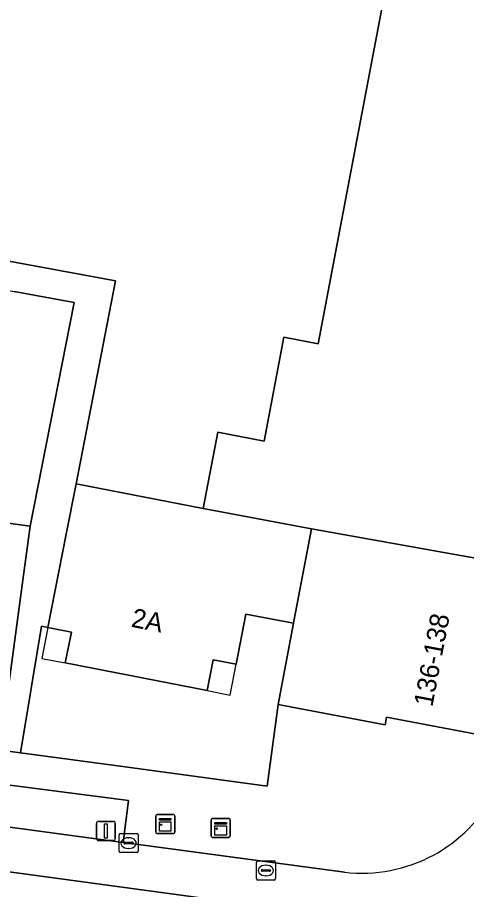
# Model space of a CAD drawing. Extents: x 161402 to 161933, y 381647 to 382315.
# Drawn here: x 161811.25 to 161834.8, y 381674.43 to 381720.22 of the extents above; entities that cross this region are included whole.
import ezdxf

# ---------------------------------------------------------------- set-up
doc = ezdxf.new("R2010")
doc.units = 0
for name, color, linetype in [('IMGEO_Erf', 7, 'Continuous'), ('IMGEO_Fietspad_gesloten', 7, 'Continuous'), ('IMGEO_Groenvoorziening', 7, 'Continuous'), ('IMGEO_Kast', 7, 'Continuous'), ('IMGEO_Kolk', 7, 'Continuous'), ('IMGEO_Lichtmast', 7, 'Continuous'), ('IMGEO_Pand', 7, 'Continuous'), ('IMGEO_Pand_nummerreeks', 7, 'Continuous'), ('IMGEO_Pand_overbouw', 7, 'Continuous'), ('IMGEO_Verkeerseiland_groen', 7, 'Continuous'), ('IMGEO_Voetpad_open', 7, 'Continuous')]:
    doc.layers.add(name, color=color, linetype=linetype)

msp = doc.modelspace()

# ---------------------------------------------------------------- linework, layer by layer
at = {"layer": 'IMGEO_Erf'}
for points in [[(161801.214, 381709.179), (161816.398, 381706.393), (161814.319, 381695.735), (161820.996, 381694.433), (161821.755, 381698.436), (161824.188, 381697.974), (161825.224, 381703.428), (161827.019, 381703.087), (161830.821, 381723.103)], [(161805.528, 381694.375), (161811.92, 381693.508), (161814.221, 381705.25), (161811.08, 381705.825)]]:
    msp.add_lwpolyline(points, dxfattribs=at)
msp.add_lwpolyline([(161824.917, 381684.151), (161825.725, 381688.406), (161823.234, 381688.891), (161822.721, 381686.261), (161821.514, 381686.497), (161821.198, 381684.877), (161813.758, 381686.328), (161814.074, 381687.948), (161812.847, 381688.187), (161812.504, 381688.254), (161811.416, 381681.599), (161816.889, 381680.871), (161824.343, 381679.854)], close=True, dxfattribs=at)
at = {"layer": 'IMGEO_Fietspad_gesloten'}
for points in [[(161816.794, 381676.903), (161801.769, 381678.925), (161797.978, 381679.434), (161797.391, 381676.3)], [(161798.491, 381677.029), (161812.233, 381675.169), (161821.38, 381673.928), (161825.839, 381673.284), (161824.804, 381664.697)], [(161828.401, 381675.346), (161817.079, 381676.869), (161816.794, 381676.903)]]:
    msp.add_lwpolyline(points, dxfattribs=at)
msp.add_arc((161829.329, 381683.124), 7.834, 263.1933, 333.2373, dxfattribs=at)
at = {"layer": 'IMGEO_Groenvoorziening'}
msp.add_lwpolyline([(161780.28, 381681.817), (161783.474, 381681.383), (161797.978, 381679.434), (161801.769, 381678.925), (161816.794, 381676.903), (161817.073, 381679.111), (161780.562, 381683.829)], close=True, dxfattribs=at)
at = {"layer": 'IMGEO_Kast'}
for p, q in [((161818.502, 381677.44), (161818.502, 381678.281)), ((161818.502, 381678.281), (161818.502, 381677.44)), ((161818.577, 381678.365), (161819.418, 381678.365)), ((161819.418, 381678.365), (161818.577, 381678.365)), ((161819.502, 381678.29), (161819.502, 381677.449)), ((161819.502, 381677.449), (161819.502, 381678.29)), ((161821.412, 381677.238), (161821.412, 381678.079)), ((161821.412, 381678.079), (161821.412, 381677.238)), ((161821.487, 381678.163), (161822.328, 381678.163)), ((161822.328, 381678.163), (161821.487, 381678.163)), ((161822.412, 381678.088), (161822.412, 381677.247)), ((161822.412, 381677.247), (161822.412, 381678.088)), ((161819.427, 381677.365), (161818.586, 381677.365)), ((161818.586, 381677.365), (161819.427, 381677.365)), ((161822.337, 381677.163), (161821.496, 381677.163)), ((161821.496, 381677.163), (161822.337, 381677.163))]:
    msp.add_line(p, q, dxfattribs=at)
for points in [[(161818.697, 381678.155), (161819.297, 381678.155), (161819.297, 381678.07), (161818.697, 381678.07), (161818.697, 381678.155)], [(161818.697, 381677.98), (161819.297, 381677.98), (161819.297, 381677.491), (161818.697, 381677.491), (161818.697, 381677.98)], [(161821.607, 381677.953), (161822.207, 381677.953), (161822.207, 381677.868), (161821.607, 381677.868), (161821.607, 381677.953)], [(161821.607, 381677.778), (161822.207, 381677.778), (161822.207, 381677.289), (161821.607, 381677.289), (161821.607, 381677.778)]]:
    msp.add_lwpolyline(points, dxfattribs=at)
for centre in [(161818.781, 381677.829), (161821.691, 381677.627)]:
    msp.add_circle(centre, 0.0377, dxfattribs=at)
for centre, start, end in [((161818.58, 381678.287), 92.4484, 184.2845), ((161818.58, 381678.287), 92.4484, 184.2845), ((161819.424, 381678.287), 2.4484, 94.2845), ((161819.424, 381678.287), 2.4484, 94.2845), ((161821.49, 381678.085), 92.4484, 184.2845), ((161821.49, 381678.085), 92.4484, 184.2845), ((161822.334, 381678.085), 2.4484, 94.2845), ((161822.334, 381678.085), 2.4484, 94.2845), ((161818.58, 381677.443), 182.4484, 274.2845), ((161818.58, 381677.443), 182.4484, 274.2845), ((161819.424, 381677.443), 272.4484, 4.2845), ((161819.424, 381677.443), 272.4484, 4.2845), ((161821.49, 381677.241), 182.4484, 274.2845), ((161821.49, 381677.241), 182.4484, 274.2845), ((161822.334, 381677.241), 272.4484, 4.2845), ((161822.334, 381677.241), 272.4484, 4.2845)]:
    msp.add_arc(centre, 0.0779, start, end, dxfattribs=at)
at = {"layer": 'IMGEO_Kolk'}
for p, q in [((161816.578, 381676.443), (161816.578, 381677.295)), ((161816.653, 381677.369), (161817.505, 381677.369)), ((161817.066, 381677.149), (161817.091, 381677.149)), ((161817.579, 381677.295), (161817.579, 381676.443)), ((161816.837, 381676.863), (161816.837, 381676.875)), ((161817.275, 381676.826), (161816.877, 381676.826)), ((161816.88, 381676.912), (161817.278, 381676.912)), ((161817.321, 381676.875), (161817.321, 381676.863)), ((161817.505, 381676.369), (161816.653, 381676.369)), ((161817.089, 381676.589), (161817.064, 381676.589)), ((161823.78, 381675.004), (161823.78, 381675.856)), ((161823.855, 381675.93), (161824.707, 381675.93)), ((161824.268, 381675.71), (161824.293, 381675.71)), ((161824.781, 381675.856), (161824.781, 381675.004)), ((161824.039, 381675.424), (161824.039, 381675.436)), ((161824.477, 381675.387), (161824.079, 381675.387)), ((161824.082, 381675.473), (161824.48, 381675.473)), ((161824.523, 381675.436), (161824.523, 381675.424)), ((161824.707, 381674.93), (161823.855, 381674.93)), ((161824.291, 381675.15), (161824.266, 381675.15))]:
    msp.add_line(p, q, dxfattribs=at)
for points in [[(161816.578, 381676.443), (161816.578, 381677.295)], [(161816.653, 381677.369), (161817.505, 381677.369)], [(161817.579, 381677.295), (161817.579, 381676.443)], [(161817.505, 381676.369), (161816.653, 381676.369)], [(161823.78, 381675.004), (161823.78, 381675.856)], [(161823.855, 381675.93), (161824.707, 381675.93)], [(161824.781, 381675.856), (161824.781, 381675.004)], [(161824.707, 381674.93), (161823.855, 381674.93)]]:
    msp.add_lwpolyline(points, dxfattribs=at)
for centre, radius, start, end in [((161816.655, 381677.293), 0.0765, 91.552, 178.448), ((161816.655, 381677.293), 0.0765, 91.552, 178.448), ((161817.503, 381677.293), 0.0765, 1.552, 88.448), ((161817.503, 381677.293), 0.0765, 1.552, 88.448), ((161816.877, 381676.872), 0.0403, 85.8775, 175.7526), ((161816.874, 381676.862), 0.0366, 178.938, 274.7102), ((161817.278, 381676.869), 0.043, 264.8664, 352.4533), ((161817.282, 381676.874), 0.0386, 1.7309, 96.639), ((161816.655, 381676.445), 0.0765, 181.552, 268.448), ((161816.655, 381676.445), 0.0765, 181.552, 268.448), ((161817.503, 381676.445), 0.0765, 271.552, 358.448), ((161817.503, 381676.445), 0.0765, 271.552, 358.448), ((161823.857, 381675.854), 0.0765, 91.552, 178.448), ((161823.857, 381675.854), 0.0765, 91.552, 178.448), ((161824.705, 381675.854), 0.0765, 1.552, 88.448), ((161824.705, 381675.854), 0.0765, 1.552, 88.448), ((161824.079, 381675.433), 0.0403, 85.8775, 175.7526), ((161824.076, 381675.423), 0.0366, 178.938, 274.7102), ((161824.48, 381675.43), 0.043, 264.8664, 352.4533), ((161824.484, 381675.435), 0.0386, 1.7309, 96.639), ((161823.857, 381675.006), 0.0765, 181.552, 268.448), ((161823.857, 381675.006), 0.0765, 181.552, 268.448), ((161824.705, 381675.006), 0.0765, 271.552, 358.448), ((161824.705, 381675.006), 0.0765, 271.552, 358.448)]:
    msp.add_arc(centre, radius, start, end, dxfattribs=at)
for centre, major_axis, ratio, start_param, end_param in [((161817.065, 381676.869), (-0.387, 0.002), 0.722429, 4.712389, 7.853982), ((161817.09, 381676.869), (-0.39, 0.002), 0.717154, 1.570796, 4.712389), ((161824.267, 381675.43), (-0.387, 0.002), 0.722429, 4.712389, 7.853982), ((161824.292, 381675.43), (-0.39, 0.002), 0.717154, 1.570796, 4.712389)]:
    msp.add_ellipse(centre, major_axis=major_axis, ratio=ratio, start_param=start_param, end_param=end_param, dxfattribs=at)
at = {"layer": 'IMGEO_Lichtmast'}
for p, q in [((161815.491, 381678.005), (161816.281, 381678.005)), ((161816.281, 381678.005), (161815.491, 381678.005)), ((161815.391, 381677.105), (161815.391, 381677.905)), ((161815.391, 381677.905), (161815.391, 381677.105)), ((161816.381, 381677.905), (161816.381, 381677.105)), ((161816.381, 381677.105), (161816.381, 381677.905)), ((161816.281, 381677.005), (161815.491, 381677.005)), ((161815.491, 381677.005), (161816.281, 381677.005))]:
    msp.add_line(p, q, dxfattribs=at)
msp.add_lwpolyline([(161815.811, 381677.88), (161815.961, 381677.88), (161815.961, 381677.13), (161815.811, 381677.13), (161815.811, 381677.88)], dxfattribs=at)
for centre, start, end in [((161815.491, 381677.905), 90, 180), ((161815.491, 381677.905), 90, 180), ((161816.281, 381677.905), 0, 90), ((161816.281, 381677.905), 360, 90), ((161815.491, 381677.105), 180, 270), ((161815.491, 381677.105), 180, 270), ((161816.281, 381677.105), 270, 0), ((161816.281, 381677.105), 270, 0)]:
    msp.add_arc(centre, 0.1, start, end, dxfattribs=at)
at = {"layer": 'IMGEO_Pand'}
for points in [[(161826.668, 381693.365), (161836.743, 381691.565), (161838.428, 381700.436), (161840.209, 381700.098), (161845.322, 381727.164), (161840.41, 381728.097), (161832.066, 381729.665), (161831.52, 381726.788), (161823.785, 381728.257), (161823.085, 381724.572), (161830.821, 381723.103), (161827.019, 381703.087), (161825.224, 381703.428), (161824.188, 381697.974), (161821.755, 381698.436), (161820.996, 381694.433)], [(161826.668, 381693.365), (161820.996, 381694.433), (161814.319, 381695.735), (161813.804, 381693.095), (161812.847, 381688.187), (161814.074, 381687.948), (161813.758, 381686.328), (161821.198, 381684.877), (161821.514, 381686.497), (161822.721, 381686.261), (161823.234, 381688.891), (161825.725, 381688.406), (161825.745, 381688.512)], [(161805.528, 381694.375), (161804.442, 381686.636), (161805.108, 381686.546), (161805.076, 381686.311), (161807.987, 381685.916), (161808.013, 381686.108), (161810.864, 381685.721), (161811.536, 381690.676), (161811.92, 381693.508)], [(161826.668, 381693.365), (161825.745, 381688.512), (161825.725, 381688.406), (161824.917, 381684.151), (161830.531, 381683.085), (161830.604, 381683.472), (161835.307, 381682.579), (161837.004, 381691.515), (161836.743, 381691.565)]]:
    msp.add_lwpolyline(points, close=True, dxfattribs=at)
at = {"layer": 'IMGEO_Pand_overbouw'}
for points in [[(161813.758, 381686.328), (161814.074, 381687.948), (161812.847, 381688.187), (161812.531, 381686.567)], [(161822.721, 381686.261), (161821.514, 381686.497), (161821.198, 381684.877), (161822.405, 381684.642)]]:
    msp.add_lwpolyline(points, close=True, dxfattribs=at)
at = {"layer": 'IMGEO_Verkeerseiland_groen'}
msp.add_lwpolyline([(161821.38, 381673.928), (161812.233, 381675.169), (161798.491, 381677.029)], dxfattribs=at)
at = {"layer": 'IMGEO_Voetpad_open'}
msp.add_lwpolyline([(161800.916, 381707.496), (161803.143, 381707.088), (161803.177, 381707.272), (161807.418, 381706.495), (161811.08, 381705.825), (161814.221, 381705.25), (161811.92, 381693.508), (161811.536, 381690.676), (161810.864, 381685.721), (161810.335, 381681.743), (161811.416, 381681.599), (161812.504, 381688.254), (161812.847, 381688.187), (161813.804, 381693.095), (161814.319, 381695.735), (161816.398, 381706.393), (161801.214, 381709.179)], close=True, dxfattribs=at)
for points in [[(161785.387, 381685.06), (161781.286, 381685.605), (161780.312, 381685.735), (161780.075, 381685.73), (161774.933, 381686.404), (161774.573, 381684.604), (161774.303, 381682.604), (161775.305, 381682.472), (161780.28, 381681.817), (161780.562, 381683.829), (161817.073, 381679.111), (161816.794, 381676.903), (161817.079, 381676.869), (161828.401, 381675.346)], [(161836.324, 381679.597), (161837.329, 381681.964), (161835.307, 381682.579), (161830.604, 381683.472), (161830.531, 381683.085), (161824.917, 381684.151), (161824.343, 381679.854), (161816.889, 381680.871), (161811.416, 381681.599), (161810.335, 381681.743), (161785.387, 381685.06)]]:
    msp.add_lwpolyline(points, dxfattribs=at)
msp.add_arc((161829.329, 381683.124), 7.834, 263.1933, 333.2373, dxfattribs=at)

# ---------------------------------------------------------------- texts
at = {"layer": 'IMGEO_Pand_nummerreeks'}
for s, rotation, p in [('2A', 348.9643, (161817.171, 381688.23)), ('136-138', 79.2472, (161833.009, 381683.986))]:
    msp.add_text(s, height=1, rotation=rotation, dxfattribs=at).set_placement(p)

doc.saveas('drawing.dxf')
